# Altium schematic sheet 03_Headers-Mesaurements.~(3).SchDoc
size A4; SheetNumber: 3; SheetTotal: 2
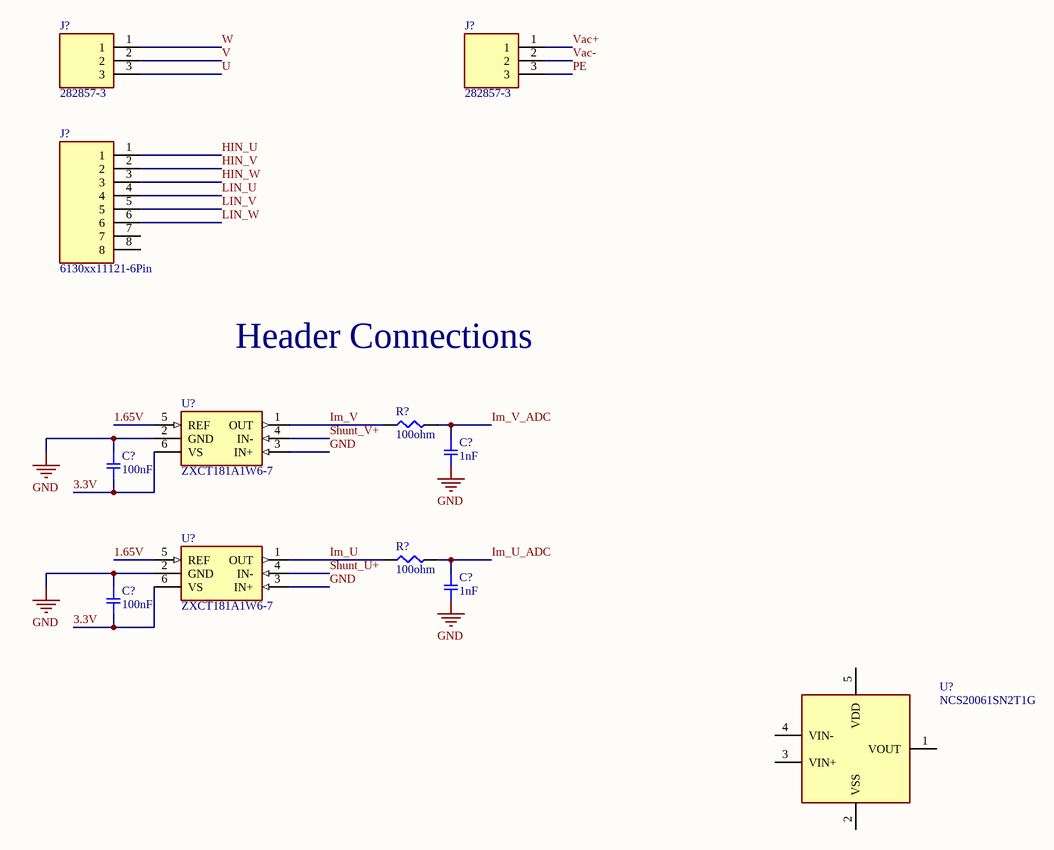
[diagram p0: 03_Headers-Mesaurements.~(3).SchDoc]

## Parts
(Parts that share a designator on the sheet are numbered #1, #2 ... from top to bottom, then left to right.)
C?#1  1nF  [006_SMD_0605]
C?#2  100nF  [006_SMD_0605]
C?#3  1nF  [006_SMD_0605]
C?#4  100nF  [006_SMD_0605]
J?#1  282857-3  [201_TE_282857-3]
J?#2  282857-3  [201_TE_282857-3]
J?#3  6130xx11121-6Pin  [200_HDRV6W64P0X254_1X6_1524X254X869P]
R?#1  100ohm  [006_SMD_0605]
R?#2  100ohm  [006_SMD_0605]
U?#1  ZXCT181A1W6-7  [896_ZXCT181A1W6-7]
U?#2  ZXCT181A1W6-7  [896_ZXCT181A1W6-7]
U?#3  NCS20061SN2T1G  [897_NCS20061SN2T1G]

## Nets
GND: C?#1.2 C?#2.1 C?#3.2 C?#4.1 U?#1.2(GND) U?#1.3(IN+) U?#2.2(GND) U?#2.3(IN+)
1.65V: U?#1.5(REF) U?#2.5(REF)
3.3V: C?#2.2 C?#4.2 U?#1.6(VS) U?#2.6(VS)
HIN_U: J?#3.1
HIN_V: J?#3.2
HIN_W: J?#3.3
Im_U: R?#2.1 U?#2.1(OUT)
Im_U_ADC: C?#3.1 R?#2.2
Im_V: R?#1.1 U?#1.1(OUT)
Im_V_ADC: C?#1.1 R?#1.2
LIN_U: J?#3.4
LIN_V: J?#3.5
LIN_W: J?#3.6
PE: J?#2.3
Shunt_U+: U?#2.4(IN-)
Shunt_V+: U?#1.4(IN-)
U: J?#1.3
V: J?#1.2
Vac+: J?#2.1
Vac-: J?#2.2
W: J?#1.1

Not connected (* = marked no-connect by the designer): J?#3 7 8; U?#3 1(VOUT) 2(VSS) 3(VIN+) 4(VIN-) 5(VDD)

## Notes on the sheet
- Header Connections

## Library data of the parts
C?#1-C?#4 = C_0605_Template: CAP CER 0605; Part Number: GC321AD72E103KX01D; Manufacturer: Murata Electronics North America; Factory Stock: 0; Unit Price (USD): 0.3; Minimum Quantity: 1; Value: 10000pF; Tolerance: ±10%; Voltage: 250V; Temperature Coefficient: X7T
J?#1 J?#2 = 282857-3: 3 Position Wire to Board Terminal Block Horizontal with Board 0.200 (5.08mm) Through Hole; MF: TE Connectivity
J?#3 = 6130xx11121-6Pin: 2.54MM PIN HEADER; Manufacturer_Name: Wurth Elektronik; Geometry.Height: 8.69mm
R?#1 R?#2 = R_0605_Template: RES SMD 0605; Part Number: ERJ-6BQF1R0V; Manufacturer: Panasonic Electronic Components; Factory Stock: 0; Unit Price (USD): 0.05834; @ qty: 1500; Minimum Quantity: 1; Value: 1; Tolerance: ±1%; Power (Watts): 0.333W, 1/3W; Temperature Coefficient: ±200ppm/°C
U?#1 U?#2 = ZXCT181A1W6-7: Bidirectional high-side current-sense amplifier, fixed gain 20 V/V, 2.7–5.5 V supply, up to 26 V common-mode input range, SOT-26 package.; MF: Texas Instruments; MP: INA181A1IDBVR
U?#3 = NCS20061SN2T1G: Single, rail-to-rail operational amplifier used as a voltage buffer for the 1.65 V current-sense reference.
